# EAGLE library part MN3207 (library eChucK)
MN3207 1024 Stage Bucket Brigade Device
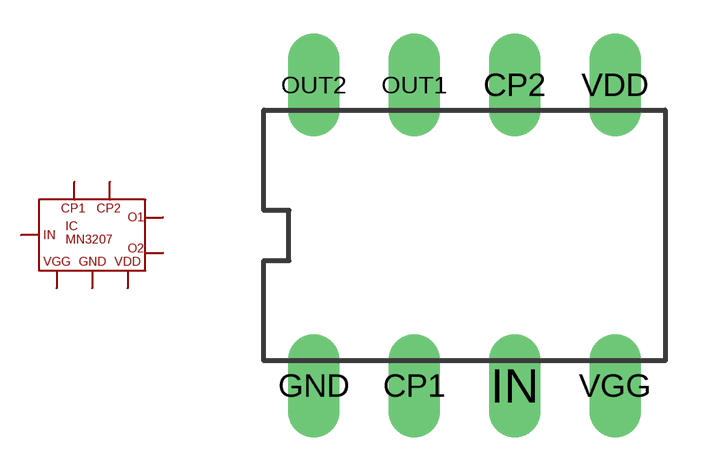
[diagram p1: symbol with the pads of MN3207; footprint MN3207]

Designator prefix IC

## MN3207  [MN3207]
CP1  CP1
CP2  CP2
GND  GND
IN  IN
OUT1  OUT1
OUT2  OUT2
VDD  VDD
VGG  VGG

## Footprint MN3207 (pad centres in mm)
drill 0.8 long: CP1 -1.27,-3.81; CP2 1.27,3.81; GND -3.81,-3.81; IN 1.27,-3.81; OUT1 -1.27,3.81; OUT2 -3.81,3.81; VDD 3.81,3.81; VGG 3.81,-3.81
